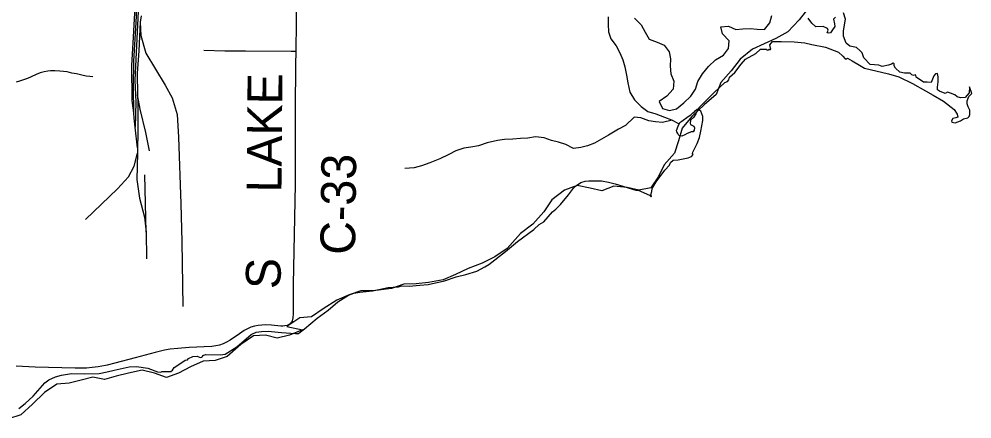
# Model space of a CAD drawing. Extents: x 63.4 to 97.4, y 0.4 to 22.4.
# Drawn here: x 66.497 to 68.052, y 14.744 to 15.396 of the extents above; entities that cross this region are included whole.
import ezdxf

# ---------------------------------------------------------------- set-up
doc = ezdxf.new("R2010")
doc.units = 0
for name, color, linetype in [('GM_X_County_Road', 7, 'Continuous'), ('GM_X_County_Road_Text', 7, 'Continuous'), ('GM_X_Major_Lake', 7, 'Continuous'), ('GM_X_Minor_River', 7, 'Continuous'), ('GM_X_Rail_Line', 7, 'Continuous'), ('GM_X_Township_Road', 7, 'Continuous'), ('SH_Cut_Line', 7, 'Continuous')]:
    doc.layers.add(name, color=color, linetype=linetype)

msp = doc.modelspace()

# ---------------------------------------------------------------- linework, layer by layer
at = {"layer": 'GM_X_County_Road'}
for points in [[(66.9495, 15.3439), (66.95, 15.3907), (66.9503, 15.4464), (66.9508, 15.4902), (66.9518, 15.5428)], [(66.4972, 14.761), (66.5076, 14.7689), (66.5204, 14.781), (66.5394, 14.8026), (66.5462, 14.8077), (66.5568, 14.8127), (66.5669, 14.8156), (66.5829, 14.8178), (66.605, 14.8177), (66.6283, 14.8183), (66.641, 14.8209), (66.6525, 14.8233), (66.6769, 14.8292), (66.6892, 14.8293), (66.7076, 14.8269), (66.7231, 14.8206), (66.7288, 14.8203), (66.7311, 14.8214), (66.745, 14.8212), (66.7478, 14.8234), (66.7508, 14.8278), (66.7628, 14.8362), (66.7686, 14.8396), (66.7721, 14.8406), (66.7738, 14.8424), (66.7811, 14.8458), (66.7881, 14.8463), (66.7928, 14.8442), (66.7956, 14.8445), (66.7966, 14.8456), (66.7972, 14.8474), (66.8024, 14.8492), (66.8261, 14.8487), (66.8337, 14.8495), (66.8528, 14.8617), (66.8762, 14.8818), (66.8843, 14.8854), (66.8933, 14.8868), (66.9042, 14.8873), (66.9256, 14.8848), (66.9488, 14.8834), (66.9532, 14.8834), (66.9569, 14.886), (66.9632, 14.8911), (66.9837, 14.9081), (67.0017, 14.9214), (67.0174, 14.9352), (67.0349, 14.9457), (67.0436, 14.9492), (67.0533, 14.9509), (67.0741, 14.9528), (67.0996, 14.9584), (67.1078, 14.9592), (67.1167, 14.9594), (67.1214, 14.9609), (67.1338, 14.9606), (67.1514, 14.9622), (67.1648, 14.9633), (67.1917, 14.9693), (67.2106, 14.9757), (67.2266, 14.9797), (67.2445, 14.9851), (67.2577, 14.992), (67.2639, 14.9959), (67.2913, 15.0171), (67.311, 15.0337), (67.3375, 15.0533), (67.346, 15.0612), (67.3499, 15.0635), (67.354, 15.0658), (67.3679, 15.082), (67.3734, 15.0864), (67.3811, 15.0937), (67.3939, 15.1098), (67.4022, 15.1207), (67.4069, 15.1251), (67.414, 15.1299), (67.4212, 15.1317), (67.4274, 15.1324), (67.4481, 15.1323), (67.4593, 15.1302), (67.4701, 15.1275), (67.5038, 15.1173), (67.508, 15.1171), (67.5261, 15.1092), (67.5287, 15.1065), (67.5295, 15.1068), (67.5284, 15.1096), (67.5303, 15.1153), (67.5304, 15.1197), (67.5373, 15.1308), (67.5515, 15.1501), (67.5591, 15.1583), (67.5603, 15.1623), (67.5649, 15.166), (67.573, 15.1666), (67.5893, 15.1701), (67.5947, 15.1723), (67.5973, 15.1755), (67.5965, 15.1771), (67.5969, 15.1791), (67.604, 15.1933), (67.6077, 15.2031), (67.6102, 15.2136), (67.6135, 15.231), (67.6132, 15.2374), (67.61, 15.2459), (67.6065, 15.2482), (67.6047, 15.2469), (67.6035, 15.2455), (67.6017, 15.2419), (67.5991, 15.2373), (67.5978, 15.2357), (67.5932, 15.2315), (67.5925, 15.2267), (67.5932, 15.2246), (67.5965, 15.2227), (67.5985, 15.2218), (67.5997, 15.2189), (67.5992, 15.2153), (67.5974, 15.2124), (67.5943, 15.2123), (67.5922, 15.2111), (67.5876, 15.2098), (67.5837, 15.2073), (67.5788, 15.2055), (67.5743, 15.2066), (67.5722, 15.2096), (67.5709, 15.2123), (67.5705, 15.2144), (67.5728, 15.2219), (67.5756, 15.2274), (67.5792, 15.2299), (67.5896, 15.2377), (67.5938, 15.2402), (67.5967, 15.2436), (67.5996, 15.2452), (67.6008, 15.2469), (67.6042, 15.2492), (67.606, 15.2498), (67.6068, 15.2515), (67.6149, 15.2599), (67.6319, 15.2766), (67.6492, 15.2927), (67.6533, 15.2945), (67.6559, 15.2974), (67.6568, 15.3014), (67.6653, 15.3094), (67.6757, 15.3229), (67.683, 15.331), (67.7, 15.3404), (67.7074, 15.3474), (67.7166, 15.3471), (67.7184, 15.3456), (67.7198, 15.3464), (67.7213, 15.3471), (67.723, 15.3463), (67.7243, 15.3473), (67.7237, 15.3489), (67.7227, 15.3544), (67.7246, 15.3574), (67.7272, 15.3601), (67.7317, 15.3596), (67.7412, 15.3596), (67.7625, 15.3595), (67.7797, 15.3578), (67.791, 15.355), (67.8133, 15.3507), (67.8349, 15.3426), (67.8419, 15.3359), (67.8457, 15.3314), (67.8479, 15.3315), (67.8493, 15.3327), (67.8571, 15.3281), (67.8688, 15.3214), (67.8769, 15.3165), (67.9161, 15.3069), (67.933, 15.3024), (67.9554, 15.2914), (67.9766, 15.2793), (67.9889, 15.2723), (68.0059, 15.2627), (68.0232, 15.249), (68.0282, 15.2415), (68.0292, 15.2366), (68.0264, 15.2352), (68.0214, 15.2341), (68.0193, 15.2302), (68.0197, 15.2281), (68.0253, 15.227), (68.0338, 15.2306), (68.0384, 15.2338), (68.0455, 15.2352), (68.0478, 15.2376), (68.049, 15.2408), (68.049, 15.2479), (68.0462, 15.2535), (68.0446, 15.2582), (68.0445, 15.2628), (68.0474, 15.2701), (68.0524, 15.2751), (68.0486, 15.2861), (68.0479, 15.2762), (68.0416, 15.2687), (68.0335, 15.268), (68.0282, 15.2698), (68.0243, 15.273), (68.0176, 15.2755), (68.0126, 15.2773), (68.0087, 15.2751), (67.9995, 15.279), (67.9964, 15.2811), (67.996, 15.2854), (67.9974, 15.2942), (67.9971, 15.3023), (67.9963, 15.3078), (67.9931, 15.3069), (67.99, 15.3037), (67.9861, 15.2931), (67.9794, 15.2935), (67.9734, 15.2935), (67.9614, 15.3016), (67.961, 15.3051), (67.9595, 15.3056), (67.9571, 15.3041), (67.9541, 15.3052), (67.9515, 15.308), (67.9426, 15.3083), (67.9349, 15.3097), (67.9278, 15.3161), (67.9255, 15.3203), (67.9254, 15.3236), (67.9236, 15.3247), (67.9211, 15.3229), (67.9165, 15.321), (67.9059, 15.3189), (67.9006, 15.321), (67.8861, 15.3225), (67.8762, 15.3331), (67.8734, 15.3415), (67.8695, 15.3451), (67.8638, 15.3499), (67.8532, 15.3521), (67.8469, 15.3574), (67.843, 15.3687), (67.8426, 15.3772), (67.8462, 15.3963), (67.8426, 15.4066)], [(67.8299, 15.3995), (67.8264, 15.3963), (67.8281, 15.3889), (67.8289, 15.3846), (67.8236, 15.3772), (67.8214, 15.3738), (67.8185, 15.3732), (67.8161, 15.3738), (67.8179, 15.3786), (67.8165, 15.3808), (67.8098, 15.3846), (67.7974, 15.3839), (67.7914, 15.3899), (67.7854, 15.3981)], [(66.9434, 14.9042), (66.9445, 14.9088), (66.9451, 14.9152), (66.9451, 14.9248), (66.9454, 14.9638), (66.9483, 15.1266), (66.9487, 15.2136), (66.9488, 15.2496), (66.9493, 15.322), (66.9495, 15.3439)], [(66.9434, 14.9042), (66.9415, 14.9012), (66.9388, 14.8986), (66.9351, 14.8965), (66.9312, 14.8957), (66.9279, 14.8953), (66.9247, 14.8954), (66.9092, 14.897), (66.9, 14.8974), (66.8938, 14.8972), (66.8877, 14.8965), (66.8817, 14.8953), (66.8759, 14.8934), (66.8702, 14.8911), (66.8649, 14.8881), (66.8571, 14.883), (66.8417, 14.8724), (66.8362, 14.8693), (66.8305, 14.8666), (66.8246, 14.8645), (66.8185, 14.863), (66.8122, 14.8623), (66.7749, 14.8606), (66.7563, 14.8591), (66.744, 14.8576), (66.7349, 14.856), (66.7198, 14.8525), (66.6868, 14.8436), (66.6537, 14.8348), (66.6414, 14.8319)], [(66.6414, 14.8319), (66.6385, 14.8312), (66.6263, 14.8289), (66.6169, 14.8278), (66.6075, 14.827), (66.5889, 14.8269), (66.5671, 14.8272), (66.5236, 14.8284), (66.4925, 14.83)]]:
    msp.add_lwpolyline(points, dxfattribs=at)
at = {"layer": 'GM_X_Major_Lake'}
msp.add_lwpolyline([(67.786, 15.4151), (67.7704, 15.3953), (67.7522, 15.3759), (67.7325, 15.3645), (67.7135, 15.3558), (67.6945, 15.3474), (67.6744, 15.3311), (67.6596, 15.3121), (67.6429, 15.2927), (67.6349, 15.2733), (67.6156, 15.2565), (67.5955, 15.2375), (67.5795, 15.2185), (67.5734, 15.1976), (67.567, 15.1778), (67.5499, 15.1588), (67.5408, 15.1398), (67.5283, 15.1208), (67.5089, 15.117), (67.4899, 15.1216), (67.4683, 15.1235), (67.4486, 15.1162), (67.4292, 15.1204), (67.4083, 15.1246), (67.3874, 15.1174), (67.367, 15.1014), (67.3537, 15.082), (67.3358, 15.0615), (67.3157, 15.0463), (67.2937, 15.0223), (67.274, 15.0086), (67.2531, 14.9983), (67.2303, 14.9892), (67.2098, 14.9797), (67.1893, 14.971), (67.1658, 14.9664), (67.1453, 14.9645), (67.1255, 14.9641), (67.1054, 14.9565), (67.0751, 14.9527), (67.0553, 14.9527), (67.036, 14.9466), (67.0162, 14.9379), (66.9938, 14.9238), (66.9745, 14.9105), (66.9555, 14.909), (66.9346, 14.8945), (66.9601, 14.8892), (66.9388, 14.8808), (66.9187, 14.8755), (66.8997, 14.8808), (66.88, 14.8797), (66.8595, 14.8656), (66.8371, 14.8458), (66.8177, 14.839), (66.798, 14.8382), (66.7771, 14.8291), (66.7574, 14.8184), (66.738, 14.8116), (66.7183, 14.8188), (66.6986, 14.8234), (66.6762, 14.8188), (66.6561, 14.8139), (66.6367, 14.8085), (66.6177, 14.812), (66.5988, 14.807), (66.579, 14.8021), (66.5589, 14.8006), (66.5388, 14.7869), (66.5195, 14.7679), (66.5001, 14.7507), (66.4804, 14.7439)], dxfattribs=at)
at = {"layer": 'GM_X_Minor_River'}
for points in [[(67.4589, 15.4002), (67.459, 15.3876), (67.4591, 15.3758), (67.4634, 15.3643), (67.4719, 15.3527), (67.4778, 15.3416), (67.4829, 15.3301), (67.486, 15.3186), (67.4888, 15.3048), (67.4911, 15.2922), (67.4939, 15.2773), (67.5016, 15.2646), (67.5127, 15.2537), (67.5236, 15.2458), (67.5368, 15.2417), (67.5508, 15.2365), (67.5621, 15.2321), (67.5745, 15.2253)], [(67.5015, 15.3977), (67.5126, 15.3868), (67.5189, 15.3749), (67.5255, 15.3637), (67.5387, 15.3589), (67.55, 15.354), (67.5585, 15.3428), (67.5605, 15.3314), (67.5599, 15.3196), (67.5611, 15.307), (67.5662, 15.2951), (67.5651, 15.2822), (67.5546, 15.2706), (67.5422, 15.2622), (67.5477, 15.2503), (67.559, 15.2473), (67.5705, 15.2501), (67.5825, 15.2597), (67.5938, 15.2709), (67.6013, 15.2818), (67.605, 15.2946), (67.6128, 15.307), (67.6223, 15.3193), (67.6339, 15.3301), (67.647, 15.3374), (67.6549, 15.3487), (67.6563, 15.3608), (67.6451, 15.3725), (67.6427, 15.3839), (67.6553, 15.3848), (67.6673, 15.3796), (67.6788, 15.3805), (67.6906, 15.381), (67.702, 15.3799), (67.7138, 15.3797), (67.7224, 15.3905), (67.7257, 15.4022)], [(66.6176, 15.3021), (66.613, 15.3025), (66.607, 15.3032), (66.6001, 15.3051), (66.5956, 15.3058), (66.591, 15.3069), (66.5834, 15.3084), (66.5762, 15.3103), (66.564, 15.3117), (66.556, 15.3121), (66.5485, 15.312), (66.5443, 15.3116), (66.5386, 15.3105), (66.5318, 15.3086), (66.5253, 15.3059), (66.5174, 15.302), (66.5113, 15.2997), (66.4984, 15.2951), (66.4927, 15.2935)], [(67.5631, 15.2315), (67.5472, 15.2278), (67.5362, 15.2288), (67.5252, 15.2306), (67.5123, 15.2351), (67.5013, 15.2365), (67.4869, 15.2227), (67.4754, 15.2169), (67.4592, 15.207), (67.448, 15.2004), (67.4365, 15.1938), (67.4253, 15.1898), (67.4142, 15.187), (67.4024, 15.1854), (67.3896, 15.1918), (67.3779, 15.1958), (67.3665, 15.1984), (67.3541, 15.2025), (67.3404, 15.2043), (67.3278, 15.2023), (67.3156, 15.2018), (67.3034, 15.2005), (67.2897, 15.1997), (67.2783, 15.1984), (67.2611, 15.1946), (67.2473, 15.1896), (67.2346, 15.1876), (67.2232, 15.1856), (67.2102, 15.1813), (67.1986, 15.1755), (67.184, 15.1686), (67.1679, 15.1617), (67.1541, 15.1571), (67.1422, 15.1539), (67.127, 15.1524)]]:
    msp.add_lwpolyline(points, dxfattribs=at)
at = {"layer": 'GM_X_Rail_Line'}
for p, q in [((66.6967, 15.4016), (66.6951, 15.3913)), ((66.6907, 15.1863), (66.6871, 15.2203)), ((66.6907, 15.1863), (66.6906, 15.1778)), ((66.7046, 15.0487), (66.7026, 15.1422)), ((66.7046, 15.0487), (66.7053, 15.0053))]:
    msp.add_line(p, q, dxfattribs=at)
for points in [[(66.6956, 15.5099), (66.693, 15.4323), (66.6865, 15.2966), (66.6879, 15.261), (66.6871, 15.2203)], [(66.6845, 15.2433), (66.6841, 15.2852), (66.6848, 15.3279), (66.6886, 15.3908), (66.6932, 15.4952)], [(66.6845, 15.2433), (66.682, 15.2638), (66.6816, 15.3209), (66.6842, 15.367), (66.6903, 15.4767)], [(66.6951, 15.3913), (66.6929, 15.3445), (66.6903, 15.308), (66.6908, 15.2728)], [(66.6951, 15.3913), (66.6963, 15.3699), (66.7043, 15.3408), (66.7359, 15.2888), (66.7475, 15.2677), (66.7554, 15.2406), (66.7578, 15.2039), (66.7616, 15.0951), (66.7632, 15.0337), (66.7646, 14.9274)], [(66.6908, 15.2728), (66.691, 15.2591), (66.6912, 15.2099), (66.6907, 15.1863)], [(66.7101, 15.1814), (66.7045, 15.2113), (66.6949, 15.2497), (66.6908, 15.2728)], [(66.6871, 15.2203), (66.6855, 15.2346), (66.6845, 15.2433)], [(66.6056, 15.0692), (66.658, 15.1193), (66.6759, 15.1388), (66.6852, 15.1563), (66.6906, 15.1778)], [(66.6906, 15.1778), (66.6898, 15.1347), (66.6939, 15.1042), (66.7023, 15.073), (66.7046, 15.0487)]]:
    msp.add_lwpolyline(points, dxfattribs=at)
at = {"layer": 'GM_X_Township_Road'}
msp.add_lwpolyline([(66.7989, 15.3455), (66.8333, 15.3447), (66.8667, 15.3445), (66.9415, 15.344), (66.9495, 15.3439)], dxfattribs=at)
at = {"layer": 'SH_Cut_Line'}
for points in [[(66.4972, 14.761), (66.5076, 14.7689), (66.5204, 14.781), (66.5394, 14.8026), (66.5462, 14.8077), (66.5568, 14.8127), (66.5669, 14.8156), (66.5829, 14.8178), (66.605, 14.8177), (66.6283, 14.8183), (66.641, 14.8209), (66.6525, 14.8233), (66.6769, 14.8292), (66.6892, 14.8293), (66.7076, 14.8269), (66.7231, 14.8206), (66.7288, 14.8203), (66.7311, 14.8214), (66.745, 14.8212), (66.7478, 14.8234), (66.7508, 14.8278), (66.7628, 14.8362), (66.7686, 14.8396), (66.7721, 14.8406), (66.7738, 14.8424), (66.7811, 14.8458), (66.7881, 14.8463), (66.7928, 14.8442), (66.7956, 14.8445), (66.7966, 14.8456), (66.7972, 14.8474), (66.8024, 14.8492), (66.8261, 14.8487), (66.8337, 14.8495), (66.8528, 14.8617), (66.8762, 14.8818), (66.8843, 14.8854), (66.8933, 14.8868), (66.9042, 14.8873), (66.9256, 14.8848), (66.9488, 14.8834), (66.9532, 14.8834), (66.9569, 14.886), (66.9632, 14.8911), (66.9837, 14.9081), (67.0017, 14.9214), (67.0174, 14.9352), (67.0349, 14.9457), (67.0436, 14.9492), (67.0533, 14.9509), (67.0741, 14.9528), (67.0996, 14.9584), (67.1078, 14.9592), (67.1167, 14.9594), (67.1214, 14.9609), (67.1338, 14.9606), (67.1514, 14.9622), (67.1648, 14.9633), (67.1917, 14.9693), (67.2106, 14.9757), (67.2266, 14.9797), (67.2445, 14.9851), (67.2577, 14.992), (67.2639, 14.9959), (67.2913, 15.0171), (67.311, 15.0337), (67.3375, 15.0533), (67.346, 15.0612), (67.3499, 15.0635), (67.354, 15.0658), (67.3679, 15.082), (67.3734, 15.0864), (67.3811, 15.0937), (67.3939, 15.1098), (67.4022, 15.1207), (67.4069, 15.1251), (67.414, 15.1299), (67.4212, 15.1317), (67.4274, 15.1324), (67.4481, 15.1323), (67.4593, 15.1302), (67.4701, 15.1275), (67.5038, 15.1173), (67.508, 15.1171), (67.5261, 15.1092), (67.5287, 15.1065), (67.5295, 15.1068), (67.5284, 15.1096), (67.5303, 15.1153), (67.5304, 15.1197), (67.5373, 15.1308), (67.5515, 15.1501), (67.5591, 15.1583), (67.5603, 15.1623), (67.5649, 15.166), (67.573, 15.1666), (67.5893, 15.1701), (67.5947, 15.1723), (67.5973, 15.1755), (67.5965, 15.1771), (67.5969, 15.1791), (67.604, 15.1933), (67.6077, 15.2031), (67.6102, 15.2136), (67.6135, 15.231), (67.6132, 15.2374), (67.61, 15.2459), (67.6065, 15.2482), (67.6047, 15.2469), (67.6035, 15.2455), (67.6017, 15.2419), (67.5991, 15.2373), (67.5978, 15.2357), (67.5932, 15.2315), (67.5925, 15.2267), (67.5932, 15.2246), (67.5965, 15.2227), (67.5985, 15.2218), (67.5997, 15.2189), (67.5992, 15.2153), (67.5974, 15.2124), (67.5943, 15.2123), (67.5922, 15.2111), (67.5876, 15.2098), (67.5837, 15.2073), (67.5788, 15.2055), (67.5743, 15.2066), (67.5722, 15.2096), (67.5709, 15.2123), (67.5705, 15.2144), (67.5728, 15.2219), (67.5756, 15.2274), (67.5792, 15.2299), (67.5896, 15.2377), (67.5938, 15.2402), (67.5967, 15.2436), (67.5996, 15.2452), (67.6008, 15.2469), (67.6042, 15.2492), (67.606, 15.2498), (67.6068, 15.2515), (67.6149, 15.2599), (67.6319, 15.2766), (67.6492, 15.2927), (67.6533, 15.2945), (67.6559, 15.2974), (67.6568, 15.3014), (67.6653, 15.3094), (67.6757, 15.3229), (67.683, 15.331), (67.7, 15.3404), (67.7074, 15.3474), (67.7166, 15.3471), (67.7184, 15.3456), (67.7198, 15.3464), (67.7213, 15.3471), (67.723, 15.3463), (67.7243, 15.3473), (67.7237, 15.3489), (67.7227, 15.3544), (67.7246, 15.3574), (67.7272, 15.3601), (67.7317, 15.3596), (67.7412, 15.3596), (67.7625, 15.3595), (67.7797, 15.3578), (67.791, 15.355), (67.8133, 15.3507), (67.8349, 15.3426), (67.8419, 15.3359), (67.8457, 15.3314), (67.8479, 15.3315), (67.8493, 15.3327), (67.8571, 15.3281), (67.8688, 15.3214), (67.8769, 15.3165), (67.9161, 15.3069), (67.933, 15.3024), (67.9554, 15.2914), (67.9766, 15.2793), (67.9889, 15.2723), (68.0059, 15.2627), (68.0232, 15.249), (68.0282, 15.2415), (68.0292, 15.2366), (68.0264, 15.2352), (68.0214, 15.2341), (68.0193, 15.2302), (68.0197, 15.2281), (68.0253, 15.227), (68.0338, 15.2306), (68.0384, 15.2338), (68.0455, 15.2352), (68.0478, 15.2376), (68.049, 15.2408), (68.049, 15.2479), (68.0462, 15.2535), (68.0446, 15.2582), (68.0445, 15.2628), (68.0474, 15.2701), (68.0524, 15.2751), (68.0486, 15.2861), (68.0479, 15.2762), (68.0416, 15.2687), (68.0335, 15.268), (68.0282, 15.2698), (68.0243, 15.273), (68.0176, 15.2755), (68.0126, 15.2773), (68.0087, 15.2751), (67.9995, 15.279), (67.9964, 15.2811), (67.996, 15.2854), (67.9974, 15.2942), (67.9971, 15.3023), (67.9963, 15.3078), (67.9931, 15.3069), (67.99, 15.3037), (67.9861, 15.2931), (67.9794, 15.2935), (67.9734, 15.2935), (67.9614, 15.3016), (67.961, 15.3051), (67.9595, 15.3056), (67.9571, 15.3041), (67.9541, 15.3052), (67.9515, 15.308), (67.9426, 15.3083), (67.9349, 15.3097), (67.9278, 15.3161), (67.9255, 15.3203), (67.9254, 15.3236), (67.9236, 15.3247), (67.9211, 15.3229), (67.9165, 15.321), (67.9059, 15.3189), (67.9006, 15.321), (67.8861, 15.3225), (67.8762, 15.3331), (67.8734, 15.3415), (67.8695, 15.3451), (67.8638, 15.3499), (67.8532, 15.3521), (67.8469, 15.3574), (67.843, 15.3687), (67.8426, 15.3772), (67.8462, 15.3963), (67.8426, 15.4066)], [(67.8299, 15.3995), (67.8264, 15.3963), (67.8281, 15.3889), (67.8289, 15.3846), (67.8236, 15.3772), (67.8214, 15.3738), (67.8185, 15.3732), (67.8161, 15.3738), (67.8179, 15.3786), (67.8165, 15.3808), (67.8098, 15.3846), (67.7974, 15.3839), (67.7914, 15.3899), (67.7854, 15.3981)]]:
    msp.add_lwpolyline(points, dxfattribs=at)

# ---------------------------------------------------------------- texts
at = {"layer": 'GM_X_County_Road_Text'}
for s, height, rotation, p in [('LAKE', 0.05682, 89.5113, (66.9256, 15.1134)), ('C-33', 0.05682, 89.3193, (67.0458, 15.0116)), ('S', 0.0568, 88.7553, (66.9239, 14.9554))]:
    msp.add_text(s, height=height, rotation=rotation, dxfattribs=at).set_placement(p)

doc.saveas('drawing.dxf')
